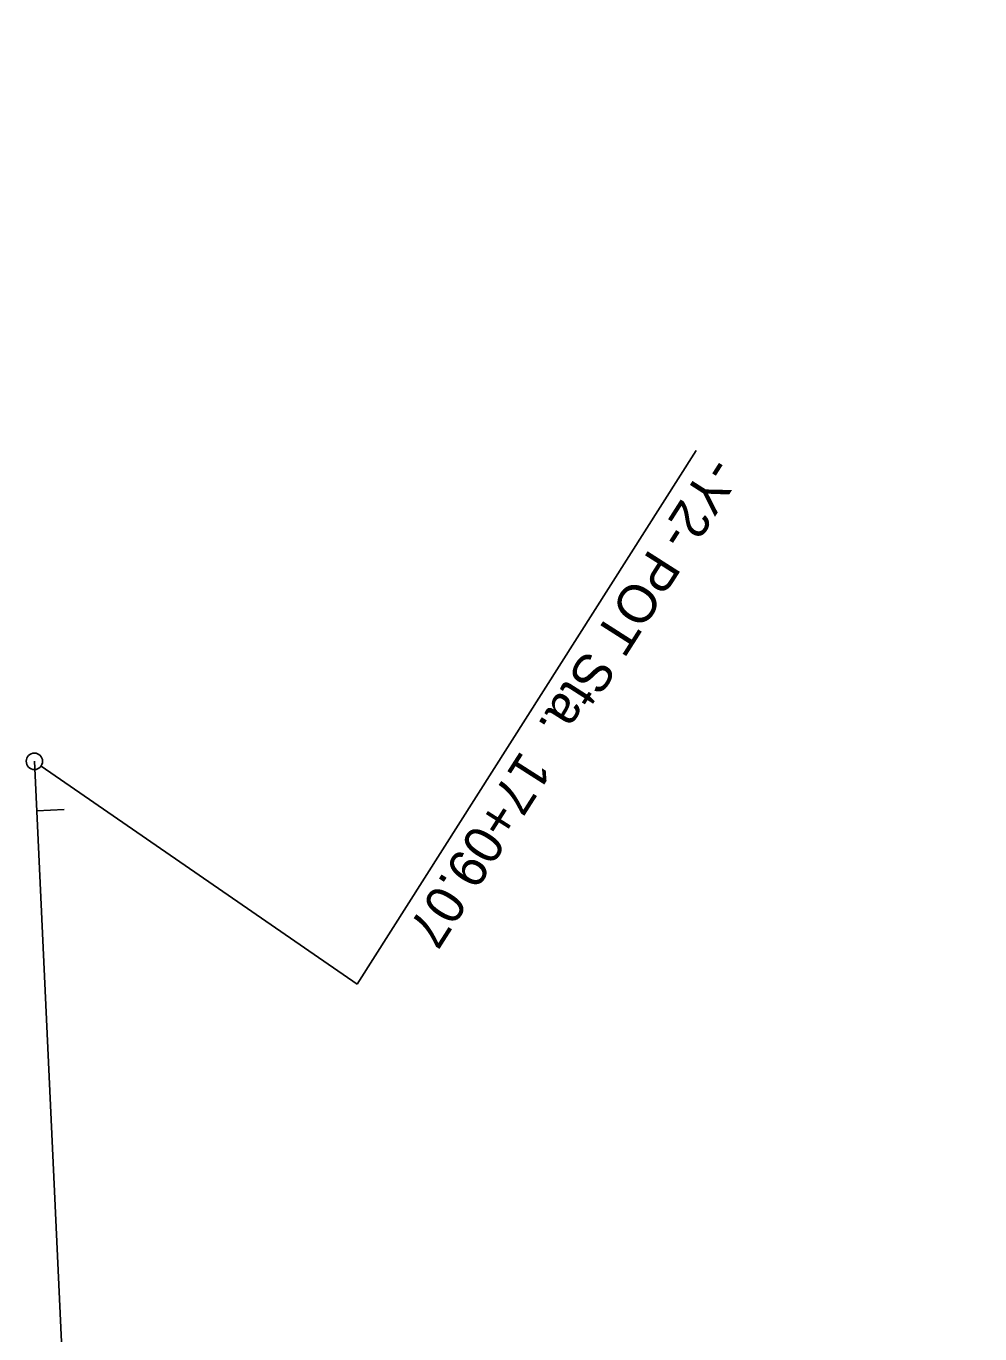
# Model space of a CAD drawing. Extents: x 1778969 to 1790720, y 807089 to 817794.
# Drawn here: x 1780909.8 to 1781084.1, y 812670.4 to 812909.4 of the extents above; entities that cross this region are included whole.
import ezdxf

# ---------------------------------------------------------------- set-up
doc = ezdxf.new("R2010")
doc.units = 0
for name, color, linetype in [('Prop EOT', 7, 'Continuous'), ('Prop Guardrail', 7, 'Continuous'), ('Prop Horizontal Alignment', 7, 'Continuous'), ('Prop Horizontal Alignment Station Label', 7, 'Continuous'), ('Prop Horizontal Alignment Tick Small', 7, 'Continuous'), ('Prop Lane Lines', 7, 'Continuous'), ('Prop Paved Shoulder', 7, 'Continuous'), ('Scratch_Level_3', 7, 'Continuous')]:
    doc.layers.add(name, color=color, linetype=linetype)

msp = doc.modelspace()

# ---------------------------------------------------------------- linework, layer by layer
at = {"layer": 'Prop EOT'}
msp.add_arc((1783308.81, 811525.98), 2350.75, 144.08998, 163.35801, dxfattribs=at)
at = {"layer": 'Prop Guardrail'}
msp.add_arc((1783308.81, 811525.98), 2358.75, 144.08998, 162.35467, dxfattribs=at)
at = {"layer": 'Prop Horizontal Alignment'}
msp.add_line((1780911.31, 812775.03), (1780935.47, 812256.86), dxfattribs=at)
msp.add_arc((1783308.81, 811525.98), 2330, 144.08998, 185.35942, dxfattribs=at)
at = {"layer": 'Prop Horizontal Alignment Station Label'}
for p, q in [((1781032.26, 812831.85), (1780970.34, 812734.28)), ((1780970.34, 812734.28), (1780912.54, 812774.17))]:
    msp.add_line(p, q, dxfattribs=at)
msp.add_circle((1780911.31, 812775.03), 1.5, dxfattribs=at)
at = {"layer": 'Prop Horizontal Alignment Tick Small'}
msp.add_line((1780911.73, 812765.97), (1780916.73, 812766.2), dxfattribs=at)
at = {"layer": 'Prop Lane Lines'}
for start in [144.36073, 148.12573]:
    msp.add_arc((1783308.81, 811525.98), 2338.75, start, 163.33829, dxfattribs=at)
at = {"layer": 'Prop Paved Shoulder'}
msp.add_arc((1783308.81, 811525.98), 2358.75, 144.08998, 162.35467, dxfattribs=at)
at = {"layer": 'Scratch_Level_3'}
msp.add_arc((1783308.81, 811525.98), 2350.75, 144.08998, 164.89021, dxfattribs=at)

# ---------------------------------------------------------------- texts
at = {"layer": 'Prop Horizontal Alignment Station Label'}
msp.add_text('-Y2- POT Sta.  17+09.07', height=7, rotation=237.4849, dxfattribs=at).set_placement((1781034.72, 812831.18))

doc.saveas('drawing.dxf')
